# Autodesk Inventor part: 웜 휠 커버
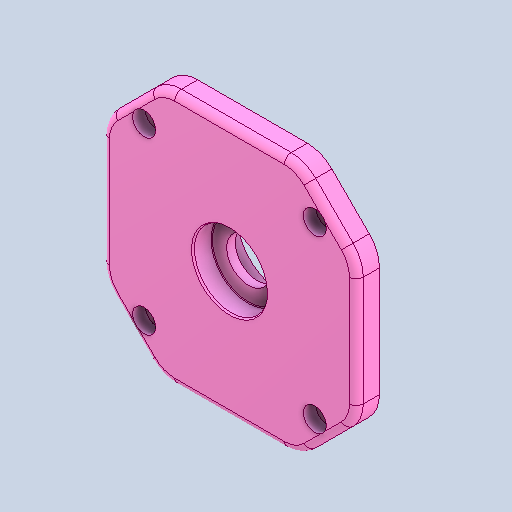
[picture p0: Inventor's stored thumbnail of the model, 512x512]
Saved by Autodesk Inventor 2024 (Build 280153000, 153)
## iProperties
Created: 2026-01
Part Number: 웜 휠 커버
Material: 알루미늄 6061
Document SubType Name: Modeling
Designer: 2-10
Density: 2.7 g/cm^3
Appearance: 기본값
Author: jhkim
Sending System: Autodesk Inventor 2026
Preprocessor: ST-DEVELOPER v20.1
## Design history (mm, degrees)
node "웜 휠 커버1"
node "솔리드2"
node "솔리드1"
